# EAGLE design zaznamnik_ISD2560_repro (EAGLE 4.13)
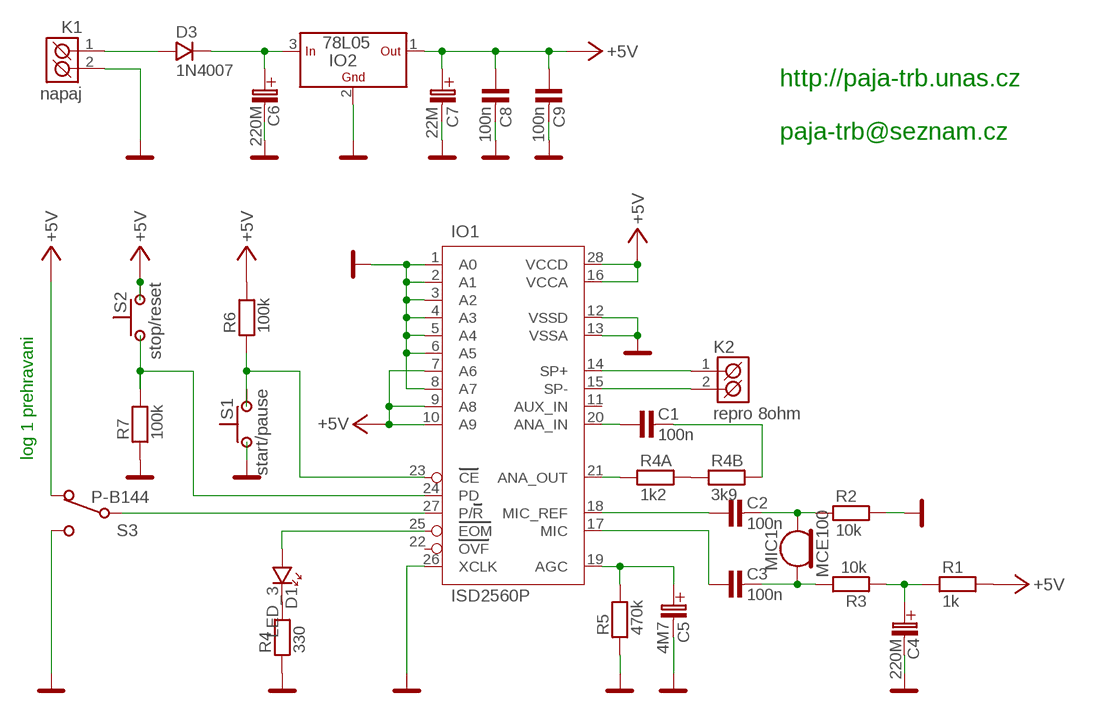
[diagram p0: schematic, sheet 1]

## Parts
C1  100n  C-KERAMIK_SMD_1206  [1206]
C2  100n  C-KERAMIK_SMD_1206  [1206]
C3  100n  C-KERAMIK_SMD_1206  [1206]
C4  220M  220M/10V  [C_EL_2,5]
C5  4M7  C-ELEKTROLYT_2  [C-EL_2]
C6  220M  220M/35V  [C_EL_5]
C7  22M  C-ELEKTROLYT_2,5  [C-EL_2,5]
C8  100n  C-KERAMIK_SMD_1206  [1206]
C9  100n  C-KERAMIK_SMD_1206  [1206]
D1  LED_3  [LED_3]
D3  1N4007  1N4007_SMD_SM-1  [SM-1]
IO1  ISD2560P  [DIL28]
IO2  78L05  78L  [TO-92]
K1  napaj  ARK500/2  [ARK500/2]
K2  repro 8ohm  ARK500/2  [ARK500/2]
MIC1  MCE100  MIC  [MIC-EL]
R1  1k  R_SMD_1206  [1206]
R2  10k  R_SMD_1206  [1206]
R3  10k  R_SMD_1206  [1206]
R4  330  R_SMD_1206  [1206]
R4A  1k2  R_SMD_1206  [1206]
R4B  3k9  R_SMD_1206  [1206]
R5  470k  R_SMD_1206  [1206]
R6  100k  R_SMD_1206  [1206]
R7  100k  R_SMD_1206  [1206]
S1  start/pause  P-DT6_KULATY_KULATY  [P-DT6]
S2  stop/reset  P-DT6_KULATY_KULATY  [P-DT6]
S3  P-B144  [P-B144]

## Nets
+5V: C7.C+(C_EL+) C8.1 C9.1 IO1.7(A6) IO1.9(A8) IO1.10(A9) IO1.16(VCCA) IO1.28(VCCD) IO2.1(OUT) R1.2 R6.2 S2.2 S2.2A S3.3
GND: C4.C-(C_EL-) C5.C-(C_EL-) C6.C-(C_EL-) C7.C-(C_EL-) C8.2 C9.2 IO1.1(A0) IO1.2(A1) IO1.3(A2) IO1.4(A3) IO1.5(A4) IO1.6(A5) IO1.8(A7) IO1.12(VSSD) IO1.13(VSSA) IO1.26(XCLK) IO2.2(GND) K1.2(K2) R2.2 R4.1 R5.1 R7.1 S1.1 S1.1A S3.1
N$1: C5.C+(C_EL+) IO1.19(AGC) R5.2
N$2: C3.1 IO1.17(MIC)
N$3: C2.1 IO1.18(MIC_REF)
N$4: IO1.21(ANA_OUT) R4A.1
N$5: C1.1 IO1.20(ANA_IN)
N$6: C1.2 R4B.2
N$7: C2.2 MIC1.MIC- R2.1
N$8: C4.C+(C_EL+) R1.1 R3.1
N$9: IO1.23(CE) R6.1 S1.2 S1.2A
N$10: D3.A K1.1(K1)
N$12: R4A.2 R4B.1
N$13: IO1.27(P/R) S3.2
N$14: C3.2 MIC1.MIC+ R3.2
N$15: IO1.14(SP+) K2.1(K1)
N$16: IO1.15(SP-) K2.2(K2)
N$17: C6.C+(C_EL+) D3.K IO2.3(IN)
N$32: D1.K R4.2
N$33: D1.A IO1.25(EOM)
S1: IO1.24(PD) R7.2 S2.1 S2.1A
Unconnected: IO1.11(AUX_IN) IO1.22(OVF)

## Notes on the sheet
- http://paja-trb.unas.cz
- paja-trb@seznam.cz
- log 1 prehravani

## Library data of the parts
C1-C3 C8 C9 = #PaJa_19:C-KERAMIK: Kondenzator - keramicky
C4 = #PaJa_C-el:220M/10V
C5 C7 = #PaJa_19:C-ELEKTROLYT: Kondenzator - elektrolyticky
C6 = #PaJa_C-el:220M/35V
D1 = #PaJa_19:LED: LED - jednobarevna
D3 = #PaJa_19:1N4007: Usmernovaci dioda - 1A, 1000V
IO1 = #PaJa_19:ISD25*: IO pro zaznam a prehravani reci 60-, 75-, 90-, a 120- sekund záznamu
IO2 = #PaJa_19:78L??: Stabilizátor - 100mA ?? - napeti => 02, 05, 06, 08, 09, 12, 15, 18
K1 K2 = #PaJa_19:ARK500/2: Svorkovnice - roztec 5mm - dvojita
MIC1 = #PaJa_19:MIC
R1-R4 R4A R4B R5-R7 = #PaJa_19:R: Rezistor
S1 S2 = #PaJa_19:P-DT6??: Tlacitkovy spinac
S3 = #PaJa_19:P-B144: Posuvny prepinac

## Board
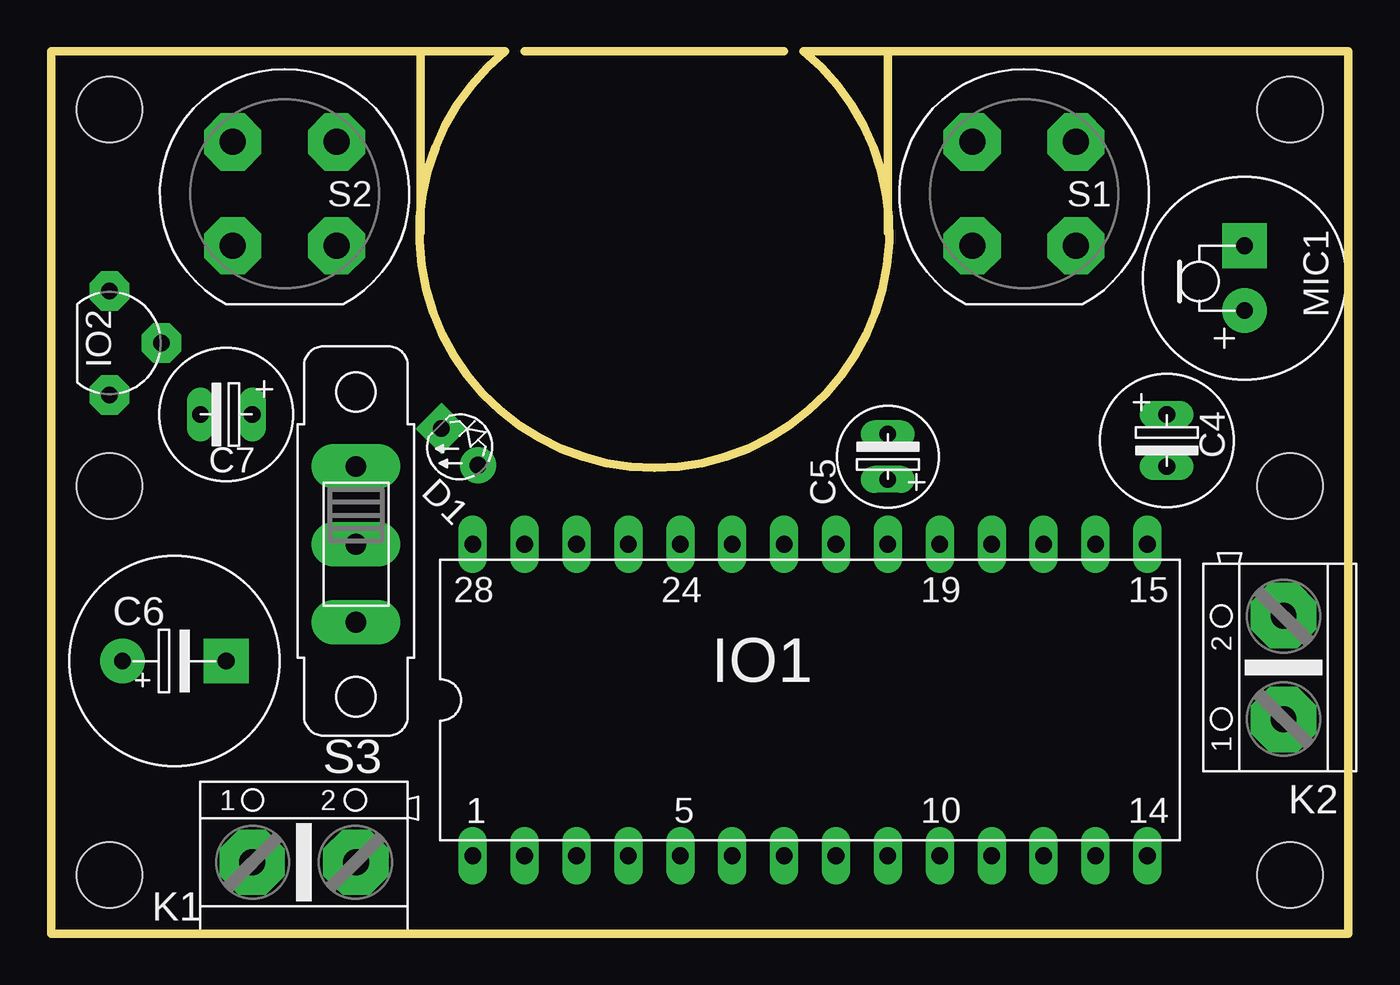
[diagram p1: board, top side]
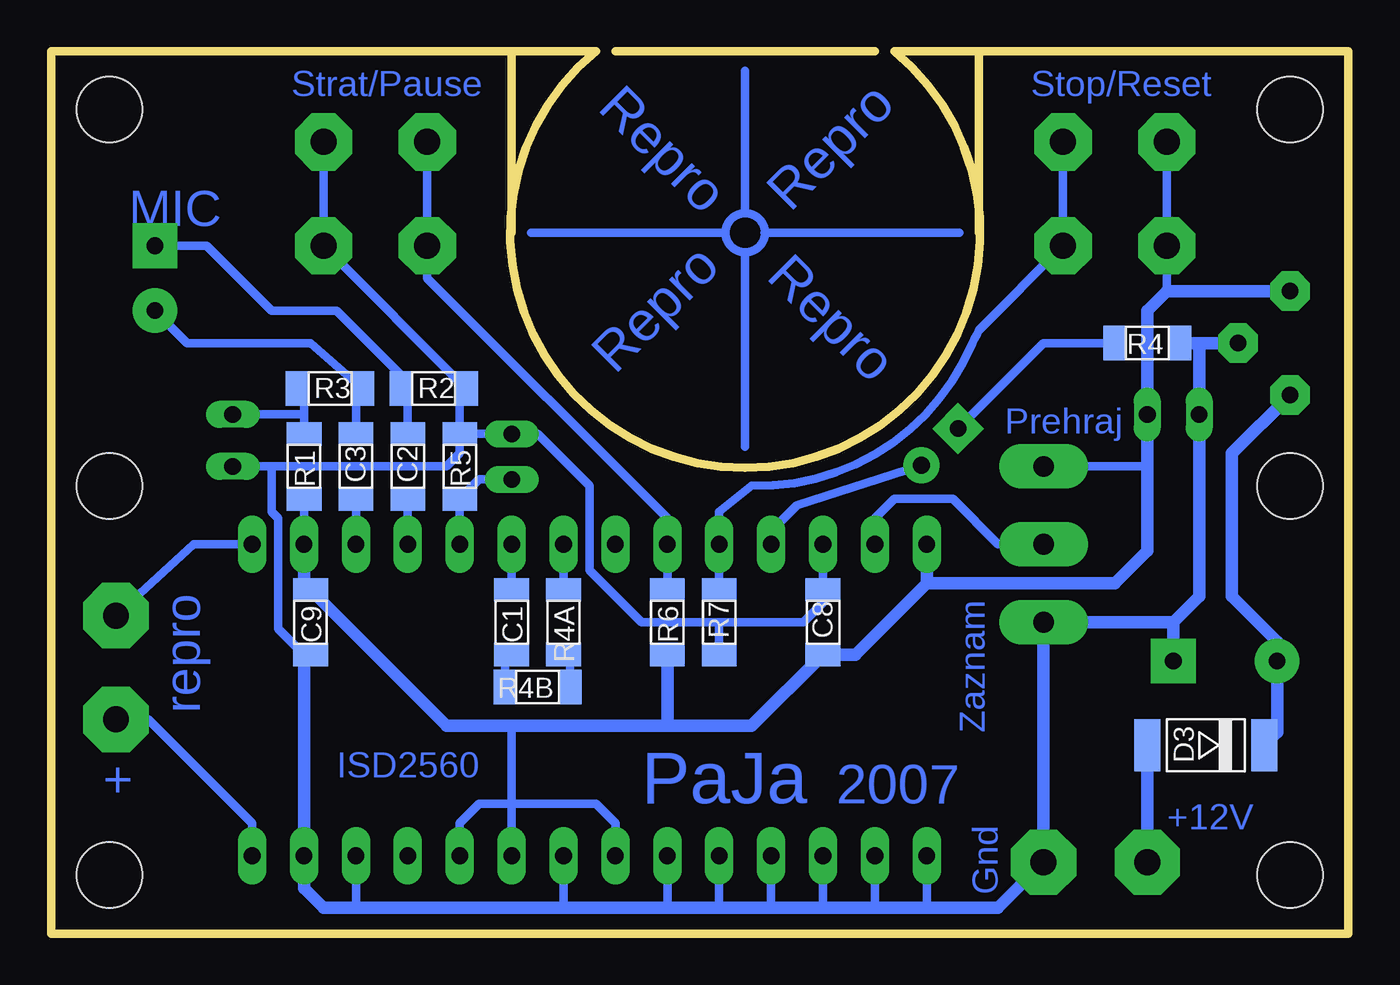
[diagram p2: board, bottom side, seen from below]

Size 63.5 x 43.18 mm. Coordinates in mm from the lower left corner, seen from the top.
Outline: 63.49,43.17 63.49,0 0,0 0,43.18 18.1,43.18
Outline: 18.1,34.29 18.1,43.18
Outline: 40.96,34.29 40.96,43.18
Outline: 63.5,43.18 40.96,43.18
Outline: 40.96,43.18 36.83,43.18 arc-281 22.23,43.18 18.1,43.18
Outline: 23.18,43.18 35.88,43.18
Copper layers (1*16): Top 0.035mm / dielectric 1.5mm / Bottom 0.035mm
Design rules "default": minimum track width 10mil, minimum drill 24mil, track to track 8mil, track to pad 8mil, pad to pad 8mil, via to via 8mil, smd to smd 8mil, copper to edge 40mil, drill to drill 8mil, minimum pad ring 10mil, minimum via ring 8mil, stop-mask expansion 4mil, vias tented up to drill 0mil, thermal gap 10mil
Holes 3.2 mm at 2.86,2.86 2.86,40.32 60.64,40.32 60.64,2.86 2.86,21.91 60.64,21.91

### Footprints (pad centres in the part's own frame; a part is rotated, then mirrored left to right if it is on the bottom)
1206 = smd 1.143 x 1.702: 1 -1.587,0; 2 1.587,0
C_EL_2,5 = drill 0.813 pad 1.27 long: C+ -1.27,0; C- 1.27,0
C-EL_2 = drill 0.813 pad 1.27 long: C+ 0,0; C- 2.223,0
C_EL_5 = drill 0.813 pad 2.184 round: C+ -2.54,0 | drill 0.813 pad 2.184 square: C- 2.54,0
C-EL_2,5 = drill 0.813 pad 1.27 long: C+ -1.27,0; C- 1.27,0
LED_3 = drill 0.813 pad 1.778 round: A -1.27,0 | drill 0.813 pad 1.778 square: K 1.27,0
SM-1 = smd 1.27 x 2.54: A 2.54,0; K -3.175,0
DIL28 = drill 0.813 pad 1.4 long: 1 -16.51,-7.62; 2 -13.97,-7.62; 3 -11.43,-7.62; 4 -8.89,-7.62; 5 -6.35,-7.62; 6 -3.81,-7.62; 7 -1.27,-7.62; 8 1.27,-7.62; 9 3.81,-7.62; 10 6.35,-7.62; 11 8.89,-7.62; 12 11.43,-7.62; 13 13.97,-7.62; 14 16.51,-7.62; 15 16.51,7.62; 16 13.97,7.62; 17 11.43,7.62; 18 8.89,7.62; 19 6.35,7.62; 20 3.81,7.62; 21 1.27,7.62; 22 -1.27,7.62; 23 -3.81,7.62; 24 -6.35,7.62; 25 -8.89,7.62; 26 -11.43,7.62; 27 -13.97,7.62; 28 -16.51,7.62
TO-92 = drill 0.813 pad 1.93 octagon: 1 0,2.54; 2 2.54,0; 3 0,-2.54
ARK500/2 = drill 1.27 pad 3.2 octagon: 1 -2.54,0; 2 2.54,0
MIC-EL = drill 0.813 pad 2.184 round: MIC+ 1.587,0 | drill 0.813 pad 2.184 square: MIC- -1.587,0
P-DT6 = drill 1.27 pad 2.8 octagon: 1 -2.54,-2.54; 1A -2.54,2.54; 2 2.54,-2.54; 2A 2.54,2.54
P-B144 = drill 1.016 pad 2.184 long: 1 -3.81,0; 2 0,0; 3 3.81,0

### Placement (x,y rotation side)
C1  40.96,15.24 270 bottom
C2  46.04,22.86 90 bottom
C3  48.58,22.86 90 bottom
C4  54.61,24.13 270 top
C5  40.96,22.23 90 top
C6  6.03,13.34 0 top
C7  8.57,25.4 180 top
C8  25.72,15.24 90 bottom
C9  50.8,15.24 270 bottom
D1  20,23.81 135 top
D3  7.3,9.21 180 bottom
IO1  37.15,11.43 0 top
IO2  2.86,28.89 0 top
K1  12.38,3.49 0 top
K2  60.33,13.02 90 top
MIC1  58.42,32.07 270 top
R1  51.12,22.86 270 bottom
R2  44.77,26.67 0 bottom
R3  49.85,26.67 0 bottom
R4  9.84,28.89 180 bottom
R4A  38.42,15.24 270 bottom
R4B  39.69,12.06 180 bottom
R5  43.5,22.86 270 bottom
R6  33.34,15.24 270 bottom
R7  30.8,15.24 90 bottom
S1  47.62,36.2 180 top
S2  11.43,36.2 180 top
S3  14.92,19.05 90 top

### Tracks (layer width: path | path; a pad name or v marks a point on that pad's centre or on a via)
+5V
  Bottom 0.406: 40.96,6.35 36.83,6.35 35.88,5.4 IO1.7 | 40.96,6.35 42.55,6.35 43.5,5.4 IO1.10 | C9.1 51.12,16.83 | 40.96,10.16 40.96,6.35 | 40.96,6.35 IO1.9 | IO1.16 R1.2 | 8.89,31.43 S2.2A S2.2 | 9.84,22.86 S3.3
  Bottom 0.61: 33.34,10.16 40.96,10.16 44.13,10.16 C9.1 | 33.34,10.16 R6.2 | 33.34,10.16 29.21,10.16 C8.1 24.13,13.65 20.64,17.14 | 51.12,16.83 IO1.16 | 20.64,17.14 IO1.28 | IO2.1 8.89,31.43 9.84,30.48 9.84,26.99 C7.C+ 9.84,22.86 9.84,18.73 11.43,17.14 20.64,17.14
GND
  Bottom 0.406: R2.2 43.5,26.35 R5.1 | R5.1 C5.C- 39.69,24.45 37.15,21.91 37.15,17.78 34.61,15.24 30.8,15.24 | 30.8,15.24 R7.1 | R5.1 43.5,23.5 44.13,22.86 52.7,22.86 | 52.7,22.86 C4.C- | 52.7,22.86 52.7,20.64 52.39,20.32 52.39,14.92 51.12,13.65 C9.2 | 30.8,15.24 26.67,15.24 25.72,16.19 C8.2 IO1.26 | 20.64,1.27 IO1.1 | 23.18,1.27 IO1.2 | 25.72,1.27 IO1.3 | 28.26,1.27 IO1.4 | 30.8,1.27 IO1.5 | 33.34,1.27 IO1.6 | 38.42,1.27 IO1.8 | 48.58,1.27 IO1.12 | R2.2 43.5,26.99 | S1.1 S1.1A R2.2
  Bottom 0.61: 51.12,13.65 IO1.13 51.12,2.22 50.16,1.27 48.58,1.27 38.42,1.27 33.34,1.27 30.8,1.27 28.26,1.27 25.72,1.27 23.18,1.27 20.64,1.27 17.14,1.27 K1.2 S3.1 8.57,15.24 | 8.57,15.24 C6.C- | 8.57,15.24 7.3,16.51 C7.C- 7.3,24.45 7.3,28.89 | 7.3,28.89 IO2.2 | 7.3,28.89 R4.1
N$1
  Bottom 0.406: C5.C+ 42.55,22.23 R5.2 IO1.19
N$2
  Bottom 0.406: IO1.17 C3.1
N$3
  Bottom 0.406: IO1.18 C2.1
N$4
  Bottom 0.406: R4A.1 IO1.21
N$5
  Bottom 0.406: C1.1 IO1.20
N$6
  Bottom 0.406: C1.2 41.27,13.65 R4B.2
N$7
  Bottom 0.406: R2.1 46.04,26.35 C2.2 | R2.1 46.04,26.67 | R2.1 46.35,27.3 49.53,30.48 52.7,30.48 55.88,33.66 MIC1.MIC-
N$8
  Bottom 0.406: R3.1 51.12,26.35 51.12,25.4 | R1.1 51.12,25.4 | 51.12,25.4 C4.C+
N$9
  Bottom 0.406: R6.1 IO1.23 33.34,20.32 45.09,32.07 S1.2A S1.2
N$10
  Bottom 0.61: K1.1 D3.A
N$11
  Bottom 0.406: 30.48,34.29 40.01,34.29
N$12
  Bottom 0.406: R4A.2 38.1,13.65 R4B.1
N$13
  Bottom 0.406: IO1.27 23.18,20.32 22.23,21.27 19.37,21.27 17.14,19.05 S3.2
N$14
  Bottom 0.406: C3.2 48.58,26.35 R3.2 50.8,28.89 56.83,28.89 MIC1.MIC+
N$15
  Bottom 0.406: K2.1 58.74,10.48 53.66,5.4 IO1.14
N$16
  Bottom 0.406: K2.2 56.52,19.05 IO1.15
N$17
  Bottom 0.61: IO2.3 5.71,23.5 5.71,16.51 3.49,14.29 C6.C+ 3.49,9.84 D3.K
N$20
  Bottom 0.406: 29.53,35.24 29.53,42.23
N$30
  Bottom 0.406: 19.05,34.29 28.57,34.29
N$31
  Bottom 0.406: 29.53,23.81 29.53,33.34
N$32
  Bottom 0.406: D1.K 14.92,28.89 R4.2
N$33
  Bottom 0.406: IO1.25 28.26,19.68 26.99,20.95 D1.A | D1.A
S1
  Bottom 0.406: R7.2 IO1.24 30.8,20.64 29.21,21.91 arc-69 18.41,28.89 arc-8 18.1,29.53 S2.1A S2.1
(copper drawn outside any net)
  shapes: Bottom circle x1

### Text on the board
Bottom: Stop/Reset | Strat/Pause | Repro | Repro | MIC | Repro | Repro | Prehraj | repro | Zaznam | ISD2560 | + | 2007 | PaJa | +12V | Gnd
